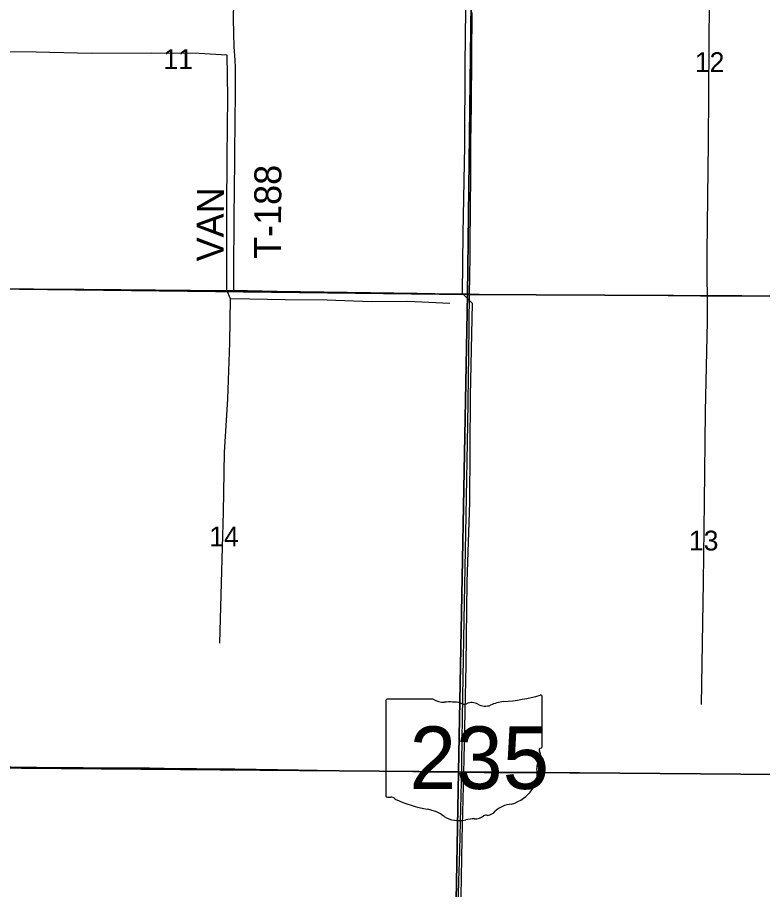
# Model space of a CAD drawing. Extents: x 1443599 to 1910620, y 1028088 to 1361369.
# Drawn here: x 1610028 to 1618321, y 1203107 to 1212815 of the extents above; entities that cross this region are included whole.
import ezdxf

# ---------------------------------------------------------------- set-up
doc = ezdxf.new("R2010")
doc.units = 0
for name, color, linetype in [('GM_X_County_Road', 7, 'Continuous'), ('GM_X_Minor_River', 7, 'Continuous'), ('GM_X_Section', 7, 'Continuous'), ('GM_X_Section_Text', 7, 'Continuous'), ('GM_X_State_Location', 7, 'Continuous'), ('GM_X_State_Route', 7, 'Continuous'), ('GM_X_State_Shield', 7, 'Continuous'), ('GM_X_Township_Road', 7, 'Continuous'), ('GM_X_Township_Road_Text', 7, 'Continuous')]:
    doc.layers.add(name, color=color, linetype=linetype)

msp = doc.modelspace()

# ---------------------------------------------------------------- linework, layer by layer
at = {"layer": 'GM_X_County_Road'}
for points in [[(1609650.8, 1204475.4), (1609674.9, 1204475.5), (1609953.9, 1204473.4), (1610528.2, 1204467.9), (1610758, 1204467), (1611299.5, 1204462.2), (1611496.5, 1204460.6), (1611660.5, 1204458), (1611857.5, 1204456.8), (1612021.5, 1204453.7), (1612448.2, 1204451.4), (1612924.1, 1204444.2), (1613153.9, 1204441.1), (1613580.5, 1204433), (1613990.7, 1204428.1), (1614253.2, 1204424), (1614597.9, 1204417.3), (1614958.7, 1204412.4), (1614972.8, 1204412.4)], [(1614972.8, 1204412.4), (1615221.3, 1204412.3), (1615549.5, 1204409.7), (1616173.2, 1204406.7), (1616747.5, 1204403), (1617272.7, 1204399.1), (1617584.5, 1204398), (1618240.9, 1204392.7), (1618716.8, 1204389.8), (1619258.3, 1204386.1), (1619668.5, 1204383.5), (1619799.9, 1204384.2), (1620062.5, 1204379.2), (1620139.7, 1204377.6), (1620210.2, 1204374.1), (1620325, 1204366.9), (1620325.3, 1204366.9)]]:
    msp.add_lwpolyline(points, dxfattribs=at)
at = {"layer": 'GM_X_Minor_River'}
for points in [[(1617853.3, 1226327.9), (1617840.1, 1225049.4), (1617825.5, 1224051.8), (1617810.7, 1222799.8), (1617798, 1221193.2), (1617782.7, 1220157.6), (1617771.2, 1218983.8), (1617758, 1217707.9), (1617748.7, 1216428), (1617736.7, 1215352.4), (1617735.8, 1213978.3), (1617725.2, 1212506.2), (1617715, 1211422.7), (1617702.4, 1210197), (1617703.6, 1209429.7), (1617680.8, 1208428.5), (1617671.9, 1207420.9), (1617660.9, 1206527.6), (1617638.1, 1205167.5)], [(1615022.5, 1213507.5), (1615006.2, 1212293.8), (1615002.9, 1211384.4), (1614984.6, 1210409.1), (1614977.5, 1209746.1), (1615087.7, 1209634), (1615068.4, 1208604.6), (1615058.5, 1207416.6), (1615029.7, 1206531.5), (1615018.3, 1205610), (1614996.7, 1204558.4), (1614973.9, 1203669.1), (1614954.2, 1202607.4), (1614937.1, 1201702)], [(1609715.8, 1212435.1), (1610236.4, 1212432), (1610847, 1212419.4), (1611523.9, 1212421.7), (1612050.5, 1212418.6), (1612358.5, 1212399.2), (1612366.6, 1211926.3), (1612357.5, 1211259.3), (1612355.6, 1210670.2), (1612352.8, 1210023.1), (1612354.8, 1209782.6), (1612397.2, 1209685.7), (1612613.4, 1209684), (1613005.8, 1209675.3), (1613474.4, 1209673.4), (1613964.7, 1209655.1), (1614373.2, 1209658.1), (1614841.5, 1209636.2)], [(1612397.2, 1209685.7), (1612387, 1209195), (1612364.5, 1208570.2), (1612328.5, 1207973.6), (1612317.3, 1207308.6), (1612294.2, 1206523.4), (1612276.9, 1205850.4)]]:
    msp.add_lwpolyline(points, dxfattribs=at)
at = {"layer": 'GM_X_Section'}
for points in [[(1609835, 1215109.4), (1615104, 1215053), (1615038.9, 1209730), (1609736, 1209792.9)], [(1615104, 1215053), (1619967.5, 1215036.6), (1620417.2, 1215002), (1620382.4, 1209704.6), (1615038.9, 1209730)], [(1615038.9, 1209730), (1614935.8, 1204419.7), (1609626.7, 1204460.7), (1609736, 1209792.9)], [(1620382.4, 1209704.6), (1620384.6, 1209584.5), (1620323, 1204373.5), (1614935.8, 1204419.7), (1615038.9, 1209730)], [(1609626.7, 1204460.7), (1614935.8, 1204419.7), (1614840.6, 1199097.2), (1609577.3, 1199123.6)], [(1614935.8, 1204419.7), (1620323, 1204373.5), (1620257.8, 1199060.6), (1614840.6, 1199097.2)]]:
    msp.add_lwpolyline(points, close=True, dxfattribs=at)
at = {"layer": 'GM_X_State_Route'}
msp.add_lwpolyline([(1614928.2, 1202727), (1614940.9, 1203202.9), (1614946.8, 1203416.1), (1614950.7, 1203547.4), (1614960.1, 1203859), (1614971.9, 1204302), (1614972.8, 1204412.4), (1614973.6, 1204531.7), (1614984.7, 1205253.8), (1614988.6, 1205467.1), (1614999.3, 1206107.2), (1615022.2, 1207272.2), (1615040.1, 1208289.7), (1615052.3, 1209061), (1615060.6, 1209737.5), (1615063, 1209930.8), (1615066.1, 1210160.5), (1615068.1, 1210406.7), (1615068.9, 1210570.9), (1615075.1, 1211178.1), (1615075.8, 1211424.3), (1615081.3, 1211834.6), (1615085.8, 1212392.6), (1615089.7, 1212868.6)], dxfattribs=at)
at = {"layer": 'GM_X_State_Shield'}
for p, q in [((1614655.7, 1205227.2), (1614146.1, 1205227.2)), ((1615869.2, 1204700.6), (1615869.2, 1205253.4)), ((1614129, 1205209), (1614129, 1204152.4)), ((1615869, 1204700.7), (1615869.2, 1204700.6))]:
    msp.add_line(p, q, dxfattribs=at)
for centre, major_axis, start_param, end_param in [((1614148.9, 1205211.2), (20.2, 0), 1.712693, 3.28349), ((1614777.1, 1205349.8), (195.5, 0), 4.042523, 4.731795), ((1615249.3, 1206667.7), (1845.5, 0), 4.814394, 5.042369), ((1615849.9, 1205255.6), (19.4, 0), 6.141152, 7.989035), ((1614841.9, 1204634), (702, 0), 1.404758, 1.657858), ((1615001.3, 1205216.7), (56.4, 0), 3.836095, 5.185415), ((1615084.1, 1205094.6), (117.3, 0), 0.950623, 2.079405), ((1615235.5, 1205262.1), (141.1, 0), 4.081561, 5.145723), ((1615484.7, 1204904.4), (371.3, 0), 1.699011, 2.107814), ((1615864.7, 1204660), (30, 0), 1.883978, 3.671073), ((1615674, 1204590.2), (180, 0), 5.934695, 6.695948), ((1615848.5, 1204698.5), (20.7, 0), 5.05454, 6.418171), ((1615938.6, 1204469.3), (130.9, 0), 2.387724, 3.262537), ((1615352.7, 1204399), (461.6, 0), 5.101752, 6.440018), ((1614149.1, 1204150), (20.3, 0), 3.00124, 4.508301), ((1614152.2, 1204258.1), (155.2, 0), 4.665946, 4.897461), ((1614183.9, 1204091.4), (56, 0), 0.519207, 1.627899), ((1614890.5, 1205040.7), (1332.7, 0), 4.195997, 4.488961), ((1615547.3, 1203855.7), (252.8, 0), 1.647645, 2.488434), ((1614493.2, 1203677.7), (417, 0), 0.823519, 1.323587), ((1615227, 1204049.9), (149.1, 0), 4.937069, 5.64225), ((1614944.2, 1204086.1), (264.6, 0), 4.026481, 4.996735), ((1615097.1, 1203720.8), (217.4, 0), 1.495662, 1.94098), ((1615116.4, 1204007), (141, 0), 4.691044, 5.507374), ((1615243.9, 1203904.7), (39.7, 0), 1.147584, 2.315152)]:
    msp.add_ellipse(centre, major_axis=major_axis, ratio=0.8, start_param=start_param, end_param=end_param, dxfattribs=at)
at = {"layer": 'GM_X_Township_Road'}
for points in [[(1612437.1, 1209776.3), (1612436.5, 1209827.4), (1612435.1, 1209975.3), (1612440, 1210583.3), (1612445.7, 1211224.2), (1612451.8, 1211733.6), (1612456.3, 1211897.9), (1612455.5, 1212045.7), (1612453.9, 1212259.4), (1612450.7, 1212341.4), (1612441.3, 1212489), (1612435.9, 1212636.8), (1612433.7, 1212801.2), (1612435, 1212981.9), (1612440.6, 1213442), (1612444.3, 1213672), (1612452.4, 1214165), (1612456.2, 1214460.8), (1612460.2, 1214805.8), (1612466, 1215025.5), (1612468.4, 1215095.4)], [(1609749.8, 1209795.4), (1609846.1, 1209796.2), (1610568.8, 1209790.4), (1610765.9, 1209788.9), (1611176.6, 1209785.9), (1611948.5, 1209780.5), (1612326.3, 1209777.2), (1612437.1, 1209776.3)], [(1612437.1, 1209776.3), (1612589.1, 1209775), (1612917.6, 1209769.1), (1614477.8, 1209745.3), (1614674.9, 1209742.6), (1615060.6, 1209737.5)], [(1615060.6, 1209737.5), (1615167.6, 1209736), (1615775.3, 1209730.9), (1616218.8, 1209727.8), (1617270, 1209720.5), (1617631.4, 1209716.8), (1618025.6, 1209715.1), (1618600.5, 1209714.7), (1619093.3, 1209712.9), (1620259.5, 1209713.2), (1620358, 1209711.5), (1620392.9, 1209710.9)]]:
    msp.add_lwpolyline(points, dxfattribs=at)

# ---------------------------------------------------------------- texts
at = {"layer": 'GM_X_Section_Text'}
for s, p in [('11', (1611652.1, 1212240.9)), ('12', (1617567.9, 1212207.3)), ('14', (1612162.5, 1206927.3)), ('13', (1617501.9, 1206881.7))]:
    msp.add_text(s, height=221, rotation=0.00001, dxfattribs=at).set_placement(p)
at = {"layer": 'GM_X_State_Location'}
msp.add_text('235', height=1, rotation=0.00001, dxfattribs=at).set_placement((1614626.5, 1204537.7))
for s in ['s', 'r']:
    msp.add_text(s, height=1, dxfattribs=at).set_placement((1614979.5, 1204610.4))
at = {"layer": 'GM_X_State_Shield'}
msp.add_text('235', height=696.1, dxfattribs=at).set_placement((1614392.6, 1204226.9))
at = {"layer": 'GM_X_Township_Road_Text'}
for s, rotation, p in [('T-188', 89.71928, (1612960.4, 1210126)), ('VAN', 89.68362, (1612321.7, 1210098.4))]:
    msp.add_text(s, height=300, rotation=rotation, dxfattribs=at).set_placement(p)

doc.saveas('drawing.dxf')
